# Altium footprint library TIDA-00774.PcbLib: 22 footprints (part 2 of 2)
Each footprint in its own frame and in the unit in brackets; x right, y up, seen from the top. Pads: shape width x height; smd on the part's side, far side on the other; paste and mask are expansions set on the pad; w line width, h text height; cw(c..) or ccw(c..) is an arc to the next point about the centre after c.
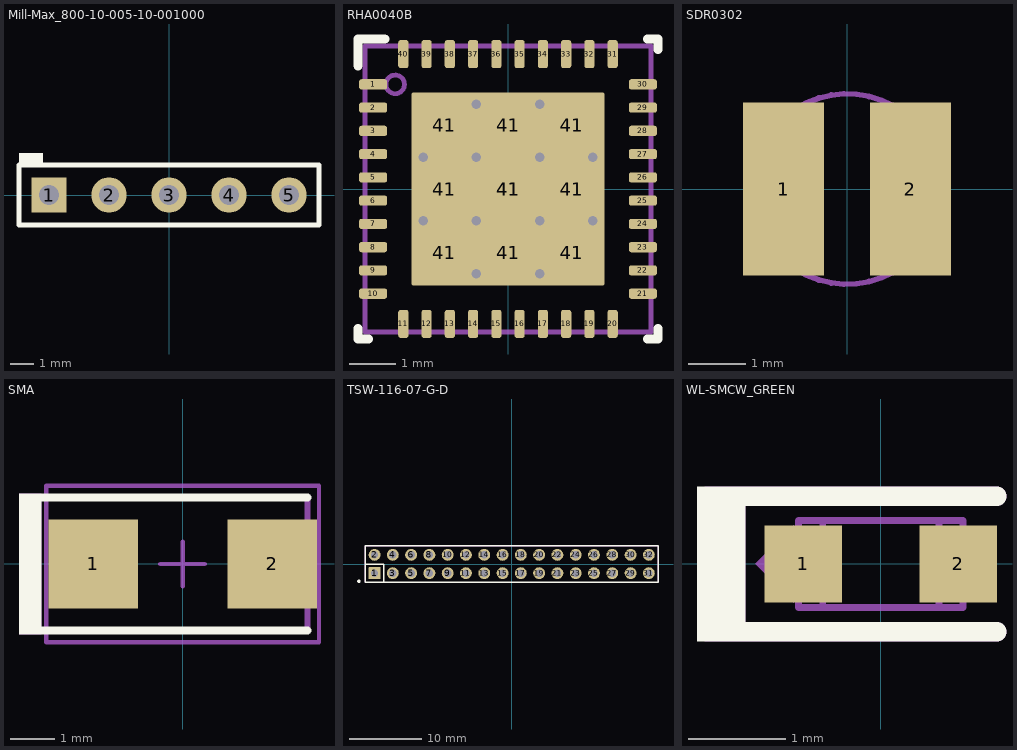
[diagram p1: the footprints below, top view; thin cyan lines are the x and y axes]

## Mill-Max_800-10-005-10-001000 [mm] "Mill-Max"
height 8.128
pads (5):
  rect 1.5x1.5 hole 0.85: 1(-5.08,0)
  round 1.5 hole 0.85: 2(-2.54,0) 3(0,0) 4(2.54,0) 5(5.08,0)
Top Overlay:
  rectangle: -6.35,1.27 -5.334,1.778
  lines w0.203: -6.35,-1.27 -6.35,1.27 6.35,1.27 6.35,-1.27 -6.35,-1.27
Mechanical 5:
  lines w0.102: -6.35,-1.27 6.35,-1.27 6.35,1.27 -6.35,1.27 -6.35,-1.27
  text ".Designator" at -2.032,-0.508 h1.02
3D body: height 3.17, standoff 0, extent -6.349,-1.269 6.349,1.269
3D body: height 0.81, standoff -3, extent -5.382,-0.304 -4.775,0.304
3D body: height 0.81, standoff -3, extent -2.842,-0.304 -2.235,0.304
3D body: height 0.81, standoff -3, extent -0.302,-0.304 0.305,0.304
3D body: height 0.81, standoff -3, extent 2.238,-0.304 2.845,0.304
3D body: height 0.81, standoff -3, extent 4.778,-0.304 5.385,0.304
3D body: height 8.13, standoff 0, extent -5.458,-0.38 -4.699,0.38
3D body: height 8.13, standoff 0, extent -2.918,-0.38 -2.159,0.38
3D body: height 8.13, standoff 0, extent -0.378,-0.38 0.381,0.38
3D body: height 8.13, standoff 0, extent 2.162,-0.38 2.921,0.38
3D body: height 8.13, standoff 0, extent 4.702,-0.38 5.461,0.38

## RHA0040B [mm] "QFN, 40-Leads, Body 6x6mm, Pitch 0.5mm, Thermal Pad 4.15 x 4.15mm, TI Recommended"
height 1
pads (50):
  rrect45% 0.6x0.22 smd mask+0.07: 1(-2.9,2.25) 2(-2.9,1.75) 3(-2.9,1.25) 4(-2.9,0.75) 5(-2.9,0.25) 6(-2.9,-0.25) 7(-2.9,-0.75) 8(-2.9,-1.25) 9(-2.9,-1.75) 10(-2.9,-2.25) 21(2.9,-2.25) 22(2.9,-1.75) 23(2.9,-1.25) 24(2.9,-0.75) 25(2.9,-0.25) 26(2.9,0.25) 27(2.9,0.75) 28(2.9,1.25) 29(2.9,1.75) 30(2.9,2.25)
  rrect45% 0.22x0.6 smd mask+0.07: 11(-2.25,-2.9) 12(-1.75,-2.9) 13(-1.25,-2.9) 14(-0.75,-2.9) 15(-0.25,-2.9) 16(0.25,-2.9) 17(0.75,-2.9) 18(1.25,-2.9) 19(1.75,-2.9) 20(2.25,-2.9) 31(2.25,2.9) 32(1.75,2.9) 33(1.25,2.9) 34(0.75,2.9) 35(0.25,2.9) 36(-0.25,2.9) 37(-0.75,2.9) 38(-1.25,2.9) 39(-1.75,2.9) 40(-2.25,2.9)
  rrect50% 1.17x1.17 on Top Paste: 41(-1.37,-1.37) 41(-1.37,0) 41(-1.37,1.37) 41(0,-1.37) 41(0,0) 41(0,1.37) 41(1.37,-1.37) 41(1.37,0) 41(1.37,1.37)
  rrect2% 4.15x4.15 smd paste-2.1: 41(0,0)
via 0.685,0.685 diameter 0.5 hole 0.2
via 1.825,0.685 diameter 0.5 hole 0.2
via -1.825,0.685 diameter 0.5 hole 0.2
via -0.685,0.685 diameter 0.5 hole 0.2
via -0.685,1.825 diameter 0.5 hole 0.2
via 0.685,1.825 diameter 0.5 hole 0.2
via 0.685,-1.825 diameter 0.5 hole 0.2
via -0.685,-1.825 diameter 0.5 hole 0.2
via -0.685,-0.685 diameter 0.5 hole 0.2
via -1.825,-0.685 diameter 0.5 hole 0.2
via 1.825,-0.685 diameter 0.5 hole 0.2
via 0.685,-0.685 diameter 0.5 hole 0.2
Top Overlay:
  lines w0.2: -3.225,-3 -3.225,-3.225 -3,-3.225 ; -3.225,2.65 -3.225,3.225 -2.65,3.225 ; 3,-3.225 3.225,-3.225 3.225,-3 ; 3,3.225 3.225,3.225 3.225,3
Mechanical 5:
  circle w0.1: c-2.425,2.25 r0.2
  lines w0.1: -3.075,-3.075 3.075,-3.075 3.075,3.075 -3.075,3.075 -3.075,-3.075
  text ".Designator" at -1.854,-0.508 h1.02
3D body "RHA0040B.stp": height 1, standoff 0, extent -3,-3 3,3

## SDR0302 [mm] "BOURNS"
height 2.8
pads (2):
  rect 1.4x3 smd: 1(-1.1,0) 2(1.1,0)
Mechanical 5:
  circle w0.1: c0,0 r1.65
  text ".Designator" at -1.4,-0.4 h0.8
3D body: height 0.8, standoff 0, extent -1.649,-1.649 1.649,1.649
3D body: height 2.4, standoff 0.8, extent -1.449,-1.449 1.449,1.449
3D body: height 2.8, standoff 2.4, extent -1.649,-1.649 1.649,1.649

## SMA [mm] "Molded Diode, 2-Leads, Body 4.3x2.6mm, IPC Medium Density, based on OnSemi component dimensions and land pattern"
height 2.27
pads (2):
  rect 2x2 smd: 1(-2,0) 2(2,0)
Top Overlay:
  rectangle: -3.658,-1.575 -3.15,1.575
  lines w0.178: -3.327,-1.486 2.794,-1.486 ; -3.327,1.486 2.794,1.486
Mechanical 5:
  rectangle: -3.658,-1.575 -3.15,1.575
  lines w0.127: -3.327,-1.486 2.794,-1.486 2.794,1.486 -3.327,1.486
  text ".Designator" at -2.769,-0.33 h1.02
Mechanical 15:
  lines w0.1: -0.5,0 0.5,0 ; 0,-0.5 0,0.5 ; -3.05,-1.75 3.05,-1.75 3.05,1.75 -3.05,1.75 -3.05,-1.75
3D body "SMA_nominal.stp": height 2.42, standoff 0.02, extent -2.6,-1.3 2.6,1.3

## TSW-116-07-G-D [mm] "Samtec 100mil, 2x16, 230 mil above insulator"
height 8.382
pads (32):
  rrect6% 1.65x1.65 hole 1.016: 1(-19.05,-1.27)
  round 1.65 hole 1.016: 2(-19.05,1.27) 3(-16.51,-1.27) 4(-16.51,1.27) 5(-13.97,-1.27) 6(-13.97,1.27) 7(-11.43,-1.27) 8(-11.43,1.27) 9(-8.89,-1.27) 10(-8.89,1.27) 11(-6.35,-1.27) 12(-6.35,1.27) 13(-3.81,-1.27) 14(-3.81,1.27) 15(-1.27,-1.27) 16(-1.27,1.27) 17(1.27,-1.27) 18(1.27,1.27) 19(3.81,-1.27) 20(3.81,1.27) 21(6.35,-1.27) 22(6.35,1.27) 23(8.89,-1.27) 24(8.89,1.27) 25(11.43,-1.27) 26(11.43,1.27) 27(13.97,-1.27) 28(13.97,1.27) 29(16.51,-1.27) 30(16.51,1.27) 31(19.05,-1.27) 32(19.05,1.27)
Top Overlay:
  circle w0.25: c-21.22,-2.4 r0.125
  lines w0.178: -20.32,0 -17.78,0 -17.78,-2.54 ; -20.32,-2.54 20.32,-2.54 20.32,2.54 -20.32,2.54 -20.32,-2.54
Mechanical 5:
  rectangle: -19.558,-1.778 -18.542,-0.762
  lines w0.127: -20.32,-2.54 -20.32,2.54 20.32,2.54 20.32,-2.54 -20.32,-2.54
  text ".Designator" at -1.524,-0.508 h1.02
3D body "SamtecTSW-07_16x2.stp": height 8.38, standoff -2.54, extent -20.32,-2.54 20.32,2.54

## WL-SMCW_GREEN [mm] "WURTH"
height 0.8
pads (2):
  rect 0.8x0.8 smd: 1(-0.8,0) 2(0.8,0)
Top Overlay:
  rectangle: -1.9,-0.8 -1.4,0.8
  lines w0.2: -1.6,-0.7 1.2,-0.7 ; -1.6,0.7 1.2,0.7
Mechanical 5:
  region: -0.9,-0.4 -0.9,0.4 -1.3,0
  lines w0.2: -1.65,-0.7 -1.65,0.55 ; 1.2,-0.7 -1.5,-0.7 ; 1.2,0.7 -1.5,0.7 ; -1.5,-0.7 -1.8,-0.7 -1.8,0.7 -1.5,0.7 ; -1.5,-0.7 -1.5,0.7
  text ".Designator" at -0.8,-0.3 h0.45
Mechanical 13:
  lines w0.07: -0.6,-0.45 -0.6,0.45 ; 0.6,-0.45 0.6,0.45 ; -0.85,-0.45 0.85,-0.45 0.85,0.45 -0.85,0.45 -0.85,-0.45
3D body: height 0.8, standoff 0.35, extent -0.599,-0.449 0.599,0.449
3D body: height 0.35, standoff 0, extent 0.601,-0.449 0.849,0.449
3D body: height 0.35, standoff 0, extent -0.599,-0.449 0.599,0.449
3D body: height 0.35, standoff 0, extent -0.849,-0.449 -0.601,0.449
